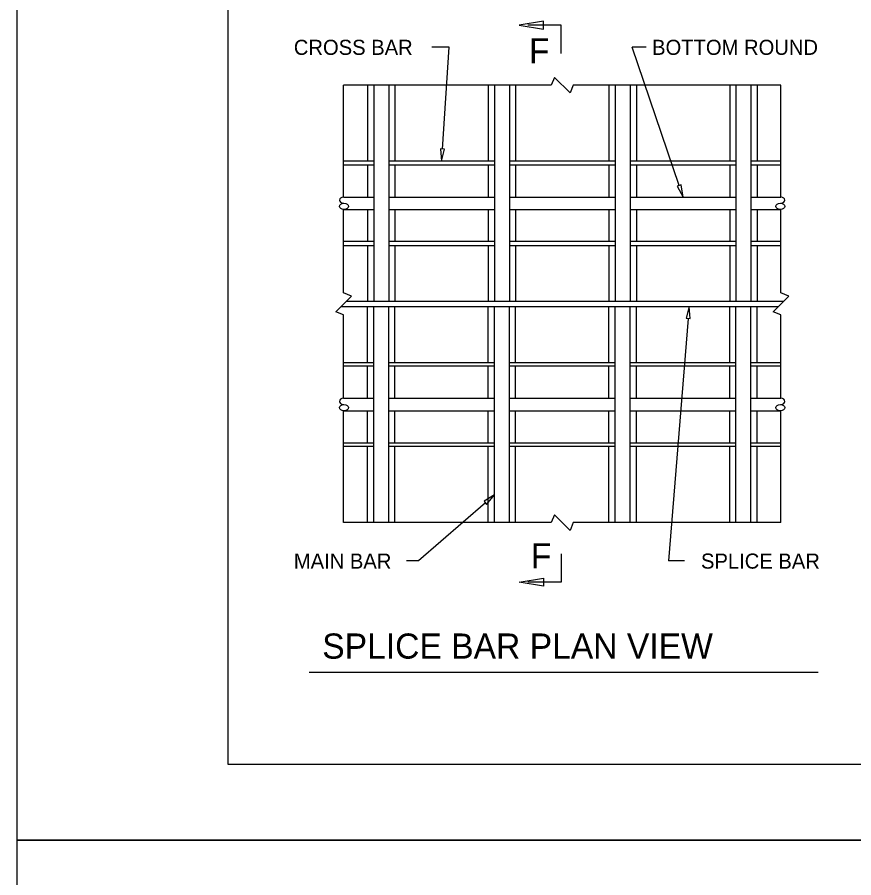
# Model space of a CAD drawing. Extents: x -24512 to -22484, y 4569 to 6351.
# Drawn here: x -24179.8 to -24013.4, y 5155.5 to 5326.6 of the extents above; entities that cross this region are included whole.
import ezdxf

# ---------------------------------------------------------------- set-up
doc = ezdxf.new("R2010")
doc.units = 0
for name, color, linetype in [('10', 7, 'Continuous'), ('2', 7, 'Continuous'), ('3', 7, 'Continuous'), ('4', 7, 'Continuous'), ('9', 7, 'Continuous'), ('PLT-BNDY', 7, 'Continuous')]:
    doc.layers.add(name, color=color, linetype=linetype)

msp = doc.modelspace()

# ---------------------------------------------------------------- linework, layer by layer
at = {"layer": '10'}
msp.add_line((-24020.51, 5196.36), (-24121.73, 5196.36), dxfattribs=at)
for centre, major_axis, start_param, end_param in [((-24114.79, 5290.24), (0.895, 0), 1.692197, 4.591233), ((-24028.03, 5290.24), (-0.895, 0), 1.691952, 4.590988), ((-24114.79, 5250.24), (0.895, 0), 1.692197, 4.591233), ((-24028.03, 5250.24), (-0.895, 0), 1.691952, 4.590988)]:
    msp.add_ellipse(centre, major_axis=major_axis, ratio=0.699516, start_param=start_param, end_param=end_param, dxfattribs=at)
for centre, major_axis in [((-24114.79, 5288.99), (0.895, 0)), ((-24028.03, 5288.99), (-0.895, 0)), ((-24114.79, 5248.99), (0.895, 0)), ((-24028.03, 5248.99), (-0.895, 0))]:
    msp.add_ellipse(centre, major_axis=major_axis, ratio=0.699516, dxfattribs=at)
at = {"layer": '2'}
for p, q in [((-24137.79, 5178.04), (-24137.79, 5740.63)), ((-23353.75, 5178.04), (-24137.79, 5178.04))]:
    msp.add_line(p, q, dxfattribs=at)
at = {"layer": '3'}
for points in [[(-24075.1, 5324.22), (-24075.1, 5325.83), (-24079.95, 5325.02)], [(-24075.1, 5215.11), (-24075.1, 5213.49), (-24079.95, 5214.3)]]:
    msp.add_lwpolyline(points, close=True, dxfattribs=at)
for points in [[(-24071.63, 5319.36), (-24071.63, 5325.02), (-24078.22, 5325.02)], [(-24071.63, 5219.96), (-24071.63, 5214.3), (-24078.22, 5214.3)]]:
    msp.add_lwpolyline(points, dxfattribs=at)
at = {"layer": '4'}
for p, q in [((-24114.86, 5290.86), (-24114.86, 5313.09)), ((-24110.11, 5313.09), (-24110.11, 5297.99)), ((-24108.88, 5313.09), (-24108.88, 5270.12)), ((-24105.9, 5313.09), (-24105.9, 5270.12)), ((-24104.67, 5313.09), (-24104.67, 5297.99)), ((-24086.11, 5313.09), (-24086.11, 5297.99)), ((-24084.88, 5313.09), (-24084.88, 5270.12)), ((-24081.9, 5313.09), (-24081.9, 5270.12)), ((-24080.67, 5313.09), (-24080.67, 5297.99)), ((-24062.11, 5313.09), (-24062.11, 5297.99)), ((-24060.88, 5313.09), (-24060.88, 5270.12)), ((-24057.91, 5313.09), (-24057.91, 5270.12)), ((-24056.67, 5313.09), (-24056.67, 5297.99)), ((-24038.11, 5313.09), (-24038.11, 5297.99)), ((-24036.88, 5313.09), (-24036.88, 5270.12)), ((-24033.91, 5313.09), (-24033.91, 5270.12)), ((-24032.67, 5313.09), (-24032.67, 5297.99)), ((-24027.92, 5290.86), (-24027.92, 5313.09)), ((-24108.88, 5297.99), (-24114.86, 5297.99)), ((-24084.88, 5297.99), (-24105.9, 5297.99)), ((-24060.88, 5297.99), (-24081.9, 5297.99)), ((-24036.88, 5297.99), (-24057.91, 5297.99)), ((-24027.92, 5297.99), (-24033.91, 5297.99)), ((-24114.86, 5297.24), (-24108.88, 5297.24)), ((-24110.11, 5297.24), (-24110.11, 5290.86)), ((-24105.9, 5297.24), (-24084.88, 5297.24)), ((-24104.67, 5297.24), (-24104.67, 5290.86)), ((-24086.11, 5297.24), (-24086.11, 5290.86)), ((-24081.9, 5297.24), (-24060.88, 5297.24)), ((-24080.67, 5297.24), (-24080.67, 5290.86)), ((-24062.11, 5297.24), (-24062.11, 5290.86)), ((-24057.91, 5297.24), (-24036.88, 5297.24)), ((-24056.67, 5297.24), (-24056.67, 5290.86)), ((-24038.11, 5297.24), (-24038.11, 5290.86)), ((-24033.91, 5297.24), (-24027.92, 5297.24)), ((-24032.67, 5297.24), (-24032.67, 5290.86)), ((-24114.86, 5290.86), (-24108.88, 5290.86)), ((-24105.9, 5290.86), (-24084.88, 5290.86)), ((-24081.9, 5290.86), (-24060.88, 5290.86)), ((-24057.91, 5290.86), (-24036.88, 5290.86)), ((-24033.91, 5290.86), (-24027.92, 5290.86)), ((-24114.86, 5288.36), (-24108.88, 5288.36)), ((-24110.11, 5288.36), (-24110.11, 5281.99)), ((-24105.9, 5288.36), (-24084.88, 5288.36)), ((-24104.67, 5288.36), (-24104.67, 5281.99)), ((-24086.11, 5288.36), (-24086.11, 5281.99)), ((-24081.9, 5288.36), (-24060.88, 5288.36)), ((-24080.67, 5288.36), (-24080.67, 5281.99)), ((-24062.11, 5288.36), (-24062.11, 5281.99)), ((-24057.91, 5288.36), (-24036.88, 5288.36)), ((-24056.67, 5288.36), (-24056.67, 5281.99)), ((-24038.11, 5288.36), (-24038.11, 5281.99)), ((-24033.91, 5288.36), (-24027.92, 5288.36)), ((-24032.67, 5288.36), (-24032.67, 5281.99)), ((-24108.88, 5281.99), (-24114.86, 5281.99)), ((-24114.86, 5281.24), (-24108.88, 5281.24)), ((-24110.11, 5281.24), (-24110.11, 5270.12)), ((-24084.88, 5281.99), (-24105.9, 5281.99)), ((-24105.9, 5281.24), (-24084.88, 5281.24)), ((-24104.67, 5281.24), (-24104.67, 5270.12)), ((-24086.11, 5281.24), (-24086.11, 5270.12)), ((-24060.88, 5281.99), (-24081.9, 5281.99)), ((-24081.9, 5281.24), (-24060.88, 5281.24)), ((-24080.67, 5281.24), (-24080.67, 5270.12)), ((-24062.11, 5281.24), (-24062.11, 5270.12)), ((-24036.88, 5281.99), (-24057.91, 5281.99)), ((-24057.91, 5281.24), (-24036.88, 5281.24)), ((-24056.67, 5281.24), (-24056.67, 5270.12)), ((-24038.11, 5281.24), (-24038.11, 5270.12)), ((-24027.92, 5281.99), (-24033.91, 5281.99)), ((-24033.91, 5281.24), (-24027.92, 5281.24)), ((-24032.67, 5281.24), (-24032.67, 5270.12)), ((-24115.36, 5269.12), (-24028.42, 5269.12)), ((-24027.42, 5270.12), (-24114.36, 5270.12)), ((-24110.11, 5257.99), (-24110.11, 5269.12)), ((-24108.88, 5226.14), (-24108.88, 5269.12)), ((-24105.9, 5226.14), (-24105.9, 5269.12)), ((-24104.67, 5257.99), (-24104.67, 5269.12)), ((-24086.11, 5257.99), (-24086.11, 5269.12)), ((-24084.88, 5226.14), (-24084.88, 5269.12)), ((-24081.9, 5226.14), (-24081.9, 5269.12)), ((-24080.67, 5257.99), (-24080.67, 5269.12)), ((-24062.11, 5257.99), (-24062.11, 5269.12)), ((-24060.88, 5226.14), (-24060.88, 5269.12)), ((-24057.91, 5226.14), (-24057.91, 5269.12)), ((-24056.67, 5257.99), (-24056.67, 5269.12)), ((-24038.11, 5257.99), (-24038.11, 5269.12)), ((-24036.88, 5226.14), (-24036.88, 5269.12)), ((-24033.91, 5226.14), (-24033.91, 5269.12)), ((-24032.67, 5257.99), (-24032.67, 5269.12)), ((-24114.86, 5257.99), (-24108.88, 5257.99)), ((-24108.88, 5257.24), (-24114.86, 5257.24)), ((-24110.11, 5250.87), (-24110.11, 5257.24)), ((-24105.9, 5257.99), (-24084.88, 5257.99)), ((-24084.88, 5257.24), (-24105.9, 5257.24)), ((-24104.67, 5250.87), (-24104.67, 5257.24)), ((-24086.11, 5250.87), (-24086.11, 5257.24)), ((-24081.9, 5257.99), (-24060.88, 5257.99)), ((-24060.88, 5257.24), (-24081.9, 5257.24)), ((-24080.67, 5250.87), (-24080.67, 5257.24)), ((-24062.11, 5250.87), (-24062.11, 5257.24)), ((-24057.91, 5257.99), (-24036.88, 5257.99)), ((-24036.88, 5257.24), (-24057.91, 5257.24)), ((-24056.67, 5250.87), (-24056.67, 5257.24)), ((-24038.11, 5250.87), (-24038.11, 5257.24)), ((-24033.91, 5257.99), (-24027.92, 5257.99)), ((-24027.92, 5257.24), (-24033.91, 5257.24)), ((-24032.67, 5250.87), (-24032.67, 5257.24)), ((-24114.86, 5250.87), (-24108.88, 5250.87)), ((-24105.9, 5250.87), (-24084.88, 5250.87)), ((-24081.9, 5250.87), (-24060.88, 5250.87)), ((-24057.91, 5250.87), (-24036.88, 5250.87)), ((-24033.91, 5250.87), (-24027.92, 5250.87)), ((-24114.86, 5248.37), (-24108.88, 5248.37)), ((-24114.86, 5226.14), (-24114.86, 5248.37)), ((-24110.11, 5241.99), (-24110.11, 5248.37)), ((-24105.9, 5248.37), (-24084.88, 5248.37)), ((-24104.67, 5241.99), (-24104.67, 5248.37)), ((-24086.11, 5241.99), (-24086.11, 5248.37)), ((-24081.9, 5248.37), (-24060.88, 5248.37)), ((-24080.67, 5241.99), (-24080.67, 5248.37)), ((-24062.11, 5241.99), (-24062.11, 5248.37)), ((-24057.91, 5248.37), (-24036.88, 5248.37)), ((-24056.67, 5241.99), (-24056.67, 5248.37)), ((-24038.11, 5241.99), (-24038.11, 5248.37)), ((-24033.91, 5248.37), (-24027.92, 5248.37)), ((-24032.67, 5241.99), (-24032.67, 5248.37)), ((-24027.92, 5226.14), (-24027.92, 5248.37)), ((-24114.86, 5241.99), (-24108.88, 5241.99)), ((-24108.88, 5241.24), (-24114.86, 5241.24)), ((-24110.11, 5226.14), (-24110.11, 5241.24)), ((-24105.9, 5241.99), (-24084.88, 5241.99)), ((-24084.88, 5241.24), (-24105.9, 5241.24)), ((-24104.67, 5226.14), (-24104.67, 5241.24)), ((-24086.11, 5226.14), (-24086.11, 5241.24)), ((-24081.9, 5241.99), (-24060.88, 5241.99)), ((-24060.88, 5241.24), (-24081.9, 5241.24)), ((-24080.67, 5226.14), (-24080.67, 5241.24)), ((-24062.11, 5226.14), (-24062.11, 5241.24)), ((-24057.91, 5241.99), (-24036.88, 5241.99)), ((-24036.88, 5241.24), (-24057.91, 5241.24)), ((-24056.67, 5226.14), (-24056.67, 5241.24)), ((-24038.11, 5226.14), (-24038.11, 5241.24)), ((-24033.91, 5241.99), (-24027.92, 5241.99)), ((-24027.92, 5241.24), (-24033.91, 5241.24)), ((-24032.67, 5226.14), (-24032.67, 5241.24))]:
    msp.add_line(p, q, dxfattribs=at)
for points in [[(-24027.92, 5313.09), (-24069.2, 5313.09), (-24069.84, 5311.54), (-24072.94, 5314.64), (-24073.58, 5313.09), (-24114.86, 5313.09)], [(-24114.86, 5250.87), (-24114.86, 5267.42), (-24116.41, 5268.06), (-24113.31, 5271.17), (-24114.86, 5271.81), (-24114.86, 5288.36)], [(-24027.92, 5250.87), (-24027.92, 5267.42), (-24029.47, 5268.06), (-24026.37, 5271.17), (-24027.92, 5271.81), (-24027.92, 5288.36)], [(-24027.92, 5226.14), (-24069.2, 5226.14), (-24069.84, 5224.59), (-24072.94, 5227.7), (-24073.58, 5226.14), (-24114.86, 5226.14)]]:
    msp.add_lwpolyline(points, dxfattribs=at)
at = {"layer": '9'}
for p, q in [((-24093.85, 5320.66), (-24097.35, 5320.66)), ((-24094.47, 5320.66), (-24096.79, 5320.66)), ((-24095.23, 5300.38), (-24093.85, 5320.66)), ((-24048.16, 5293.14), (-24057.47, 5320.66)), ((-24054.74, 5320.66), (-24057.47, 5320.66)), ((-24046.37, 5266.72), (-24050.3, 5218.54)), ((-24086.69, 5230.07), (-24099.96, 5218.54)), ((-24099.96, 5218.54), (-24102.35, 5218.54)), ((-24047.07, 5218.54), (-24050.3, 5218.54))]:
    msp.add_line(p, q, dxfattribs=at)
for points in [[(-24094.83, 5300.36), (-24095.63, 5300.41), (-24095.39, 5297.99)], [(-24047.78, 5293.27), (-24048.54, 5293.01), (-24047.39, 5290.86)], [(-24046.77, 5266.76), (-24045.97, 5266.69), (-24046.17, 5269.12)], [(-24086.95, 5230.37), (-24086.43, 5229.77), (-24084.88, 5231.65)]]:
    msp.add_lwpolyline(points, close=True, dxfattribs=at)
at = {"layer": 'PLT-BNDY'}
for points in [[(-24179.75, 5757.04), (-23338.75, 5757.04), (-23338.75, 5163.04), (-24179.75, 5163.04)], [(-24179.75, 5163.04), (-23338.75, 5163.04), (-23338.75, 4569.04), (-24179.75, 4569.04)]]:
    msp.add_lwpolyline(points, close=True, dxfattribs=at)

# ---------------------------------------------------------------- texts
at = {"layer": '9'}
for s, height, p in [('CROSS BAR', 3, (-24124.76, 5319.11)), ('F', 5, (-24078.02, 5317.41)), ('BOTTOM ROUND', 2.9999, (-24053.54, 5319.11)), ('F', 5, (-24077.63, 5217.03)), ('MAIN BAR', 3, (-24124.76, 5216.99)), ('SPLICE BAR', 3, (-24043.82, 5216.99)), ('SPLICE BAR PLAN VIEW', 5, (-24119.12, 5199.1))]:
    msp.add_text(s, height=height, dxfattribs=at).set_placement(p)

doc.saveas('drawing.dxf')
